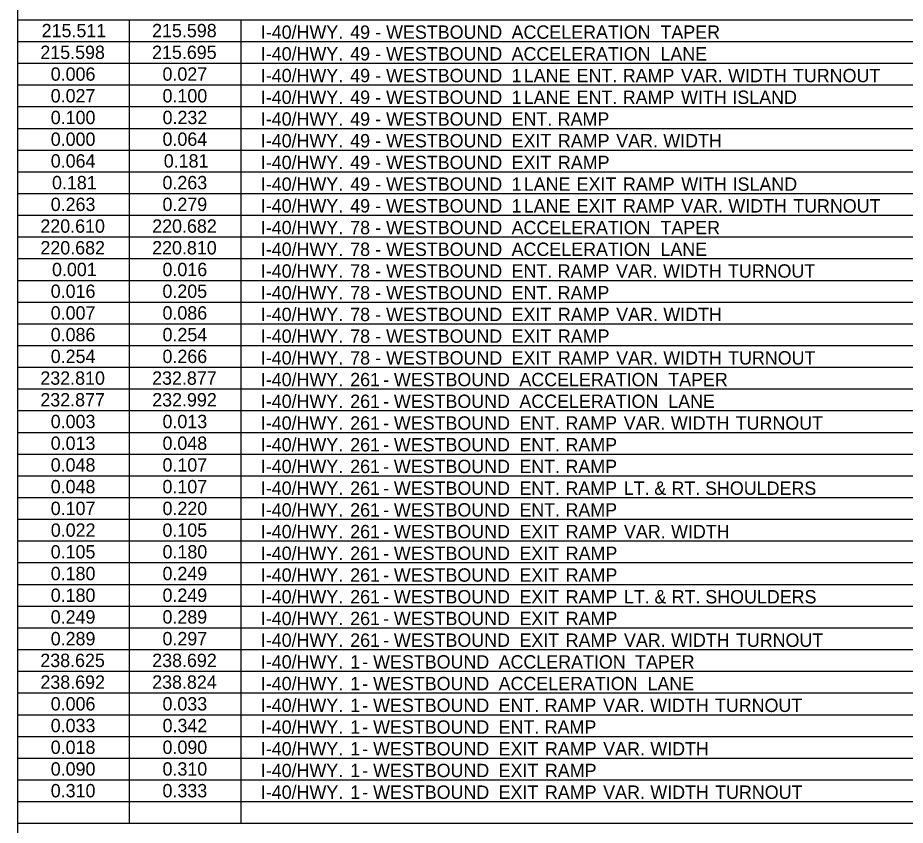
# Model space of a CAD drawing. Extents: x 2261867 to 2275370, y -3124789 to -3122260.
# Drawn here: x 2269380.5 to 2269779.2, y -3122908.5 to -3122546 of the extents above; entities that cross this region are included whole.
import ezdxf

# ---------------------------------------------------------------- set-up
doc = ezdxf.new("R2010")
doc.units = 0
doc.layers.add('Default', color=7, linetype='Continuous')

msp = doc.modelspace()

# ---------------------------------------------------------------- linework, layer by layer
at = {"layer": 'Default'}
for p, q in [((2269380.47, -3123434.1), (2269380.47, -3122273.85)), ((2269380.47, -3123434.1), (2269380.47, -3122273.85)), ((2269380.47, -3122546.85), (2270507.08, -3122546.85)), ((2269430.68, -3122897.85), (2269430.68, -3122546.85)), ((2269430.68, -3122907.6), (2269430.68, -3122546.85)), ((2269480.89, -3122888.1), (2269480.89, -3122546.85)), ((2269480.89, -3122907.6), (2269480.89, -3122546.85)), ((2269380.47, -3122556.6), (2270507.08, -3122556.6)), ((2269380.47, -3122566.35), (2270507.08, -3122566.35)), ((2269380.47, -3122576.1), (2270507.08, -3122576.1)), ((2269380.47, -3122585.85), (2270507.08, -3122585.85)), ((2269380.47, -3122595.6), (2270507.08, -3122595.6)), ((2269380.47, -3122605.35), (2270507.08, -3122605.35)), ((2269380.47, -3122615.1), (2270507.08, -3122615.1)), ((2269380.47, -3122624.85), (2270507.08, -3122624.85)), ((2269380.47, -3122634.6), (2270507.08, -3122634.6)), ((2269380.47, -3122644.35), (2270507.08, -3122644.35)), ((2269380.47, -3122654.1), (2270507.08, -3122654.1)), ((2269380.47, -3122663.85), (2270507.08, -3122663.85)), ((2269380.47, -3122673.6), (2270507.08, -3122673.6)), ((2269380.47, -3122683.35), (2270507.08, -3122683.35)), ((2269380.47, -3122693.1), (2270507.08, -3122693.1)), ((2269380.47, -3122702.85), (2270507.08, -3122702.85)), ((2269380.47, -3122712.6), (2270507.08, -3122712.6)), ((2269380.47, -3122722.35), (2270507.08, -3122722.35)), ((2269380.47, -3122732.1), (2270507.08, -3122732.1)), ((2269380.47, -3122741.85), (2270507.08, -3122741.85)), ((2269380.47, -3122751.6), (2270507.08, -3122751.6)), ((2269380.47, -3122761.35), (2270507.08, -3122761.35)), ((2269380.47, -3122771.1), (2270507.08, -3122771.1)), ((2269380.47, -3122780.85), (2270507.08, -3122780.85)), ((2269380.47, -3122790.6), (2270507.08, -3122790.6)), ((2269380.47, -3122800.35), (2270507.08, -3122800.35)), ((2269380.47, -3122810.1), (2270507.08, -3122810.1)), ((2269380.47, -3122819.85), (2270507.08, -3122819.85)), ((2269380.47, -3122829.6), (2270507.08, -3122829.6)), ((2269380.47, -3122839.35), (2270507.08, -3122839.35)), ((2269380.47, -3122849.1), (2270507.08, -3122849.1)), ((2269380.47, -3122858.85), (2270507.08, -3122858.85)), ((2269380.47, -3122868.6), (2270507.08, -3122868.6)), ((2269380.47, -3122878.35), (2270507.08, -3122878.35)), ((2269380.47, -3122888.1), (2270507.08, -3122888.1)), ((2269380.47, -3122897.85), (2270507.08, -3122897.85)), ((2269480.89, -3122907.6), (2269480.89, -3122897.85)), ((2269380.47, -3122907.6), (2270507.08, -3122907.6)), ((2269480.89, -3122907.6), (2269790.46, -3122907.6))]:
    msp.add_line(p, q, dxfattribs=at)

# ---------------------------------------------------------------- texts
for s, p in [('215.511', (2269391.2, -3122554.72)), ('215.598', (2269440.83, -3122554.72)), ('I-40/HWY.', (2269489.67, -3122555.4)), (' 49', (2269527.59, -3122555.4)), (' -', (2269538.87, -3122555.4)), (' WESTBOUND', (2269543.72, -3122555.4)), (' ACCELERATION', (2269600.1, -3122555.4)), (' TAPER', (2269666.97, -3122555.4)), ('215.598', (2269390.62, -3122564.47)), ('215.695', (2269440.81, -3122564.47)), ('I-40/HWY.', (2269489.67, -3122565.15)), (' 49', (2269527.59, -3122565.15)), (' WESTBOUND', (2269543.72, -3122565.15)), (' ACCELERATION', (2269600.1, -3122565.15)), (' LANE', (2269666.97, -3122565.15)), (' -', (2269538.87, -3122565.15)), ('0.006', (2269395.28, -3122574.22)), ('0.027', (2269445.49, -3122574.22)), ('I-40/HWY.', (2269489.67, -3122574.9)), (' 49', (2269527.59, -3122574.9)), (' -', (2269538.87, -3122574.9)), (' WESTBOUND', (2269543.72, -3122574.9)), (' 1', (2269600.1, -3122574.9)), (' LANE', (2269605.55, -3122574.9)), (' ENT.', (2269629.33, -3122574.9)), (' RAMP', (2269650.02, -3122574.9)), (' VAR.', (2269676.21, -3122574.9)), (' WIDTH', (2269697.37, -3122574.9)), (' TURNOUT', (2269726.5, -3122574.9)), ('0.027', (2269395.28, -3122583.97)), ('0.100', (2269445.51, -3122583.97)), ('I-40/HWY.', (2269489.67, -3122584.65)), (' 49', (2269527.59, -3122584.65)), (' WESTBOUND', (2269543.72, -3122584.65)), (' 1', (2269600.1, -3122584.65)), (' LANE', (2269605.55, -3122584.65)), (' ENT.', (2269629.33, -3122584.65)), (' RAMP', (2269650.02, -3122584.65)), (' WITH', (2269676.21, -3122584.65)), (' ISLAND', (2269699.28, -3122584.65)), (' -', (2269538.87, -3122584.65)), ('0.100', (2269395.29, -3122593.72)), ('0.232', (2269445.53, -3122593.72)), ('I-40/HWY.', (2269489.67, -3122594.4)), (' 49', (2269527.59, -3122594.4)), (' WESTBOUND', (2269543.72, -3122594.4)), (' ENT.', (2269600.1, -3122594.4)), (' RAMP', (2269620.8, -3122594.4)), (' -', (2269538.87, -3122594.4)), ('0.000', (2269395.29, -3122603.47)), ('0.064', (2269445.51, -3122603.47)), ('I-40/HWY.', (2269489.67, -3122604.15)), (' 49', (2269527.59, -3122604.15)), (' WESTBOUND', (2269543.72, -3122604.15)), (' EXIT', (2269600.1, -3122604.15)), (' RAMP', (2269620.9, -3122604.15)), (' VAR.', (2269647.08, -3122604.15)), (' WIDTH', (2269668.25, -3122604.15)), (' -', (2269538.87, -3122604.15)), ('0.064', (2269395.29, -3122613.22)), ('0.181', (2269446.07, -3122613.22)), ('I-40/HWY.', (2269489.67, -3122613.9)), (' 49', (2269527.59, -3122613.9)), (' WESTBOUND', (2269543.72, -3122613.9)), (' EXIT', (2269600.1, -3122613.9)), (' RAMP', (2269620.9, -3122613.9)), (' -', (2269538.87, -3122613.9)), ('0.181', (2269395.86, -3122622.97)), ('0.263', (2269445.49, -3122622.97)), ('I-40/HWY.', (2269489.67, -3122623.65)), (' 49', (2269527.59, -3122623.65)), (' WESTBOUND', (2269543.72, -3122623.65)), (' 1', (2269600.1, -3122623.65)), (' LANE', (2269605.55, -3122623.65)), (' EXIT', (2269629.33, -3122623.65)), (' RAMP', (2269650.12, -3122623.65)), (' WITH', (2269676.31, -3122623.65)), (' ISLAND', (2269699.38, -3122623.65)), (' -', (2269538.87, -3122623.65)), ('0.263', (2269395.28, -3122632.72)), ('0.279', (2269445.49, -3122632.72)), ('I-40/HWY.', (2269489.67, -3122633.4)), (' 49', (2269527.59, -3122633.4)), (' WESTBOUND', (2269543.72, -3122633.4)), (' 1', (2269600.1, -3122633.4)), (' LANE', (2269605.55, -3122633.4)), (' EXIT', (2269629.33, -3122633.4)), (' RAMP', (2269650.12, -3122633.4)), (' VAR.', (2269676.31, -3122633.4)), (' WIDTH', (2269697.47, -3122633.4)), (' TURNOUT', (2269726.6, -3122633.4)), (' -', (2269538.87, -3122633.4)), ('220.610', (2269390.63, -3122642.47)), ('220.682', (2269440.87, -3122642.47)), ('I-40/HWY.', (2269489.67, -3122643.15)), (' 78', (2269527.59, -3122643.15)), (' WESTBOUND', (2269543.72, -3122643.15)), (' ACCELERATION', (2269600.1, -3122643.15)), (' TAPER', (2269666.97, -3122643.15)), (' -', (2269538.87, -3122643.15)), ('220.682', (2269390.65, -3122652.22)), ('220.810', (2269440.84, -3122652.22)), ('I-40/HWY.', (2269489.67, -3122652.9)), (' 78', (2269527.59, -3122652.9)), (' WESTBOUND', (2269543.72, -3122652.9)), (' ACCELERATION', (2269600.1, -3122652.9)), (' LANE', (2269666.97, -3122652.9)), (' -', (2269538.87, -3122652.9)), ('0.001', (2269395.86, -3122661.97)), ('0.016', (2269445.49, -3122661.97)), ('I-40/HWY.', (2269489.67, -3122662.65)), (' 78', (2269527.59, -3122662.65)), (' -', (2269538.87, -3122662.65)), (' WESTBOUND', (2269543.72, -3122662.65)), (' ENT.', (2269600.1, -3122662.65)), (' RAMP', (2269620.8, -3122662.65)), (' VAR.', (2269646.98, -3122662.65)), (' WIDTH', (2269668.15, -3122662.65)), (' TURNOUT', (2269697.27, -3122662.65)), ('0.016', (2269395.28, -3122671.72)), ('0.205', (2269445.47, -3122671.72)), ('I-40/HWY.', (2269489.67, -3122672.4)), (' 78', (2269527.59, -3122672.4)), (' WESTBOUND', (2269543.72, -3122672.4)), (' ENT.', (2269600.1, -3122672.4)), (' RAMP', (2269620.8, -3122672.4)), (' -', (2269538.87, -3122672.4)), ('0.007', (2269395.28, -3122681.47)), ('0.086', (2269445.49, -3122681.47)), ('I-40/HWY.', (2269489.67, -3122682.15)), (' 78', (2269527.59, -3122682.15)), (' WESTBOUND', (2269543.72, -3122682.15)), (' EXIT', (2269600.1, -3122682.15)), (' RAMP', (2269620.9, -3122682.15)), (' VAR.', (2269647.08, -3122682.15)), (' WIDTH', (2269668.25, -3122682.15)), (' -', (2269538.87, -3122682.15)), ('0.086', (2269395.28, -3122691.22)), ('0.254', (2269445.51, -3122691.22)), ('I-40/HWY.', (2269489.67, -3122691.9)), (' 78', (2269527.59, -3122691.9)), (' WESTBOUND', (2269543.72, -3122691.9)), (' EXIT', (2269600.1, -3122691.9)), (' RAMP', (2269620.9, -3122691.9)), (' -', (2269538.87, -3122691.9)), ('0.254', (2269395.29, -3122700.97)), ('0.266', (2269445.49, -3122700.97)), ('I-40/HWY.', (2269489.67, -3122701.65)), (' 78', (2269527.59, -3122701.65)), (' WESTBOUND', (2269543.72, -3122701.65)), (' EXIT', (2269600.1, -3122701.65)), (' RAMP', (2269620.9, -3122701.65)), (' VAR.', (2269647.08, -3122701.65)), (' WIDTH', (2269668.25, -3122701.65)), (' TURNOUT', (2269697.37, -3122701.65)), (' -', (2269538.87, -3122701.65)), ('232.810', (2269390.63, -3122710.72)), ('232.877', (2269440.83, -3122710.72)), ('I-40/HWY.', (2269489.67, -3122711.4)), (' 261', (2269527.59, -3122711.4)), (' WESTBOUND', (2269547.21, -3122711.4)), (' ACCELERATION', (2269603.59, -3122711.4)), (' TAPER', (2269670.46, -3122711.4)), (' -', (2269542.36, -3122711.4)), ('232.877', (2269390.62, -3122720.47)), ('232.992', (2269440.87, -3122720.47)), ('I-40/HWY.', (2269489.67, -3122721.15)), (' 261', (2269527.59, -3122721.15)), (' WESTBOUND', (2269547.21, -3122721.15)), (' ACCELERATION', (2269603.59, -3122721.15)), (' LANE', (2269670.46, -3122721.15)), (' -', (2269542.36, -3122721.15)), ('0.003', (2269395.28, -3122730.22)), ('0.013', (2269445.49, -3122730.22)), ('I-40/HWY.', (2269489.67, -3122730.9)), (' 261', (2269527.59, -3122730.9)), (' WESTBOUND', (2269547.21, -3122730.9)), (' ENT.', (2269603.59, -3122730.9)), (' RAMP', (2269624.28, -3122730.9)), (' VAR.', (2269650.47, -3122730.9)), (' WIDTH', (2269671.64, -3122730.9)), (' TURNOUT', (2269700.76, -3122730.9)), (' -', (2269542.36, -3122730.9)), ('0.013', (2269395.28, -3122739.97)), ('0.048', (2269445.49, -3122739.97)), ('I-40/HWY.', (2269489.67, -3122740.65)), (' 261', (2269527.59, -3122740.65)), (' WESTBOUND', (2269547.21, -3122740.65)), (' ENT.', (2269603.59, -3122740.65)), (' RAMP', (2269624.28, -3122740.65)), (' -', (2269542.36, -3122740.65)), ('0.048', (2269395.28, -3122749.72)), ('0.107', (2269445.49, -3122749.72)), ('I-40/HWY.', (2269489.67, -3122750.4)), (' 261', (2269527.59, -3122750.4)), (' -', (2269542.36, -3122750.4)), (' WESTBOUND', (2269547.21, -3122750.4)), (' ENT.', (2269603.59, -3122750.4)), (' RAMP', (2269624.28, -3122750.4)), ('0.048', (2269395.28, -3122759.47)), ('0.107', (2269445.49, -3122759.47)), ('I-40/HWY.', (2269489.67, -3122760.15)), (' 261', (2269527.59, -3122760.15)), (' WESTBOUND', (2269547.21, -3122760.15)), (' ENT.', (2269603.59, -3122760.15)), (' RAMP', (2269624.28, -3122760.15)), (' LT.', (2269650.47, -3122760.15)), (' &', (2269664.18, -3122760.15)), (' RT.', (2269671.91, -3122760.15)), (' SHOULDERS', (2269687.01, -3122760.15)), (' -', (2269542.36, -3122760.15)), ('0.107', (2269395.28, -3122769.22)), ('0.220', (2269445.51, -3122769.22)), ('I-40/HWY.', (2269489.67, -3122769.9)), (' 261', (2269527.59, -3122769.9)), (' WESTBOUND', (2269547.21, -3122769.9)), (' ENT.', (2269603.59, -3122769.9)), (' RAMP', (2269624.28, -3122769.9)), (' -', (2269542.36, -3122769.9)), ('0.022', (2269395.31, -3122778.97)), ('0.105', (2269445.47, -3122778.97)), ('I-40/HWY.', (2269489.67, -3122779.65)), (' 261', (2269527.59, -3122779.65)), (' WESTBOUND', (2269547.21, -3122779.65)), (' EXIT', (2269603.59, -3122779.65)), (' RAMP', (2269624.39, -3122779.65)), (' VAR.', (2269650.57, -3122779.65)), (' WIDTH', (2269671.74, -3122779.65)), (' -', (2269542.36, -3122779.65)), ('0.105', (2269395.26, -3122788.72)), ('0.180', (2269445.51, -3122788.72)), ('I-40/HWY.', (2269489.67, -3122789.4)), (' 261', (2269527.59, -3122789.4)), (' WESTBOUND', (2269547.21, -3122789.4)), (' EXIT', (2269603.59, -3122789.4)), (' RAMP', (2269624.39, -3122789.4)), (' -', (2269542.36, -3122789.4)), ('0.180', (2269395.29, -3122798.47)), ('0.249', (2269445.49, -3122798.47)), ('I-40/HWY.', (2269489.67, -3122799.15)), (' 261', (2269527.59, -3122799.15)), (' WESTBOUND', (2269547.21, -3122799.15)), (' EXIT', (2269603.59, -3122799.15)), (' RAMP', (2269624.39, -3122799.15)), (' -', (2269542.36, -3122799.15)), ('0.180', (2269395.29, -3122808.22)), ('0.249', (2269445.49, -3122808.22)), ('I-40/HWY.', (2269489.67, -3122808.9)), (' 261', (2269527.59, -3122808.9)), (' WESTBOUND', (2269547.21, -3122808.9)), (' EXIT', (2269603.59, -3122808.9)), (' RAMP', (2269624.39, -3122808.9)), (' LT.', (2269650.57, -3122808.9)), (' &', (2269664.28, -3122808.9)), (' RT.', (2269672.01, -3122808.9)), (' SHOULDERS', (2269687.11, -3122808.9)), (' -', (2269542.36, -3122808.9)), ('0.249', (2269395.28, -3122817.97)), ('0.289', (2269445.49, -3122817.97)), ('I-40/HWY.', (2269489.67, -3122818.65)), (' 261', (2269527.59, -3122818.65)), (' WESTBOUND', (2269547.21, -3122818.65)), (' EXIT', (2269603.59, -3122818.65)), (' RAMP', (2269624.39, -3122818.65)), (' -', (2269542.36, -3122818.65)), ('0.289', (2269395.28, -3122827.72)), ('0.297', (2269445.49, -3122827.72)), ('I-40/HWY.', (2269489.67, -3122828.4)), (' 261', (2269527.59, -3122828.4)), (' WESTBOUND', (2269547.21, -3122828.4)), (' EXIT', (2269603.59, -3122828.4)), (' RAMP', (2269624.39, -3122828.4)), (' VAR.', (2269650.57, -3122828.4)), (' WIDTH', (2269671.74, -3122828.4)), (' TURNOUT', (2269700.86, -3122828.4)), (' -', (2269542.36, -3122828.4)), ('238.625', (2269390.6, -3122837.47)), ('238.692', (2269440.87, -3122837.47)), ('I-40/HWY.', (2269489.67, -3122838.15)), (' 1', (2269527.59, -3122838.15)), (' -', (2269533.04, -3122838.15)), (' WESTBOUND', (2269537.89, -3122838.15)), (' ACCLERATION', (2269594.27, -3122838.15)), (' TAPER', (2269655.54, -3122838.15)), ('238.692', (2269390.65, -3122847.22)), ('238.824', (2269440.85, -3122847.22)), ('I-40/HWY.', (2269489.67, -3122847.9)), (' 1', (2269527.59, -3122847.9)), (' WESTBOUND', (2269537.89, -3122847.9)), (' ACCELERATION', (2269594.27, -3122847.9)), (' LANE', (2269661.14, -3122847.9)), (' -', (2269533.04, -3122847.9)), ('0.006', (2269395.28, -3122856.97)), ('0.033', (2269445.49, -3122856.97)), ('I-40/HWY.', (2269489.67, -3122857.65)), (' 1', (2269527.59, -3122857.65)), (' WESTBOUND', (2269537.89, -3122857.65)), (' ENT.', (2269594.27, -3122857.65)), (' RAMP', (2269614.96, -3122857.65)), (' VAR.', (2269641.15, -3122857.65)), (' WIDTH', (2269662.32, -3122857.65)), (' TURNOUT', (2269691.44, -3122857.65)), (' -', (2269533.04, -3122857.65)), ('0.033', (2269395.28, -3122866.72)), ('0.342', (2269445.53, -3122866.72)), ('I-40/HWY.', (2269489.67, -3122867.4)), (' 1', (2269527.59, -3122867.4)), (' WESTBOUND', (2269537.89, -3122867.4)), (' ENT.', (2269594.27, -3122867.4)), (' RAMP', (2269614.96, -3122867.4)), (' -', (2269533.04, -3122867.4)), ('0.018', (2269395.28, -3122876.47)), ('0.090', (2269445.51, -3122876.47)), ('I-40/HWY.', (2269489.67, -3122877.15)), (' 1', (2269527.59, -3122877.15)), (' WESTBOUND', (2269537.89, -3122877.15)), (' EXIT', (2269594.27, -3122877.15)), (' RAMP', (2269615.07, -3122877.15)), (' VAR.', (2269641.25, -3122877.15)), (' WIDTH', (2269662.42, -3122877.15)), (' -', (2269533.04, -3122877.15)), ('0.090', (2269395.29, -3122886.22)), ('0.310', (2269445.51, -3122886.22)), ('I-40/HWY.', (2269489.67, -3122886.9)), (' 1', (2269527.59, -3122886.9)), (' WESTBOUND', (2269537.89, -3122886.9)), (' EXIT', (2269594.27, -3122886.9)), (' RAMP', (2269615.07, -3122886.9)), (' -', (2269533.04, -3122886.9)), ('0.310', (2269395.29, -3122895.97)), ('0.333', (2269445.49, -3122895.97)), ('I-40/HWY.', (2269489.67, -3122896.65)), (' 1', (2269527.59, -3122896.65)), (' WESTBOUND', (2269537.89, -3122896.65)), (' EXIT', (2269594.27, -3122896.65)), (' RAMP', (2269615.07, -3122896.65)), (' VAR.', (2269641.25, -3122896.65)), (' WIDTH', (2269662.42, -3122896.65)), (' TURNOUT', (2269691.54, -3122896.65)), (' -', (2269533.04, -3122896.65))]:
    msp.add_text(s, height=6, dxfattribs=at).set_placement(p)

doc.saveas('drawing.dxf')
